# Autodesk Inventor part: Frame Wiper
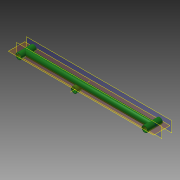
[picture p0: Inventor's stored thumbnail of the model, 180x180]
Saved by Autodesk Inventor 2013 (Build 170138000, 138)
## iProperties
Created: 2006-03
Part Number: Frame Wiper
Document SubType Name: Modeling
Designer: Autodesk, Inc.
Material: Stainless Steel, 440C
Mass: 450.336 g
Surface Area: 586.145 cm^2
Volume: 58.1078 cm^3
Density: 7.75 g/cm^3
Author: Autodesk, Inc.
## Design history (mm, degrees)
sketch "Sketch1"
  geometry: L1 (0, -28.185)-(0, 16.364) reference; L2 (-305.6, 0)-(307.6, 0) reference; C1 r 10 at (210, 0); 1 further point
  constraints: 1 centre point
  dimensions: "d3" = 20 diameter of C1; "d6" = 210 distance of C1.centre point (0, 0)
extrude "Extrusion1" new body sketch "Sketch1" stored distance "d4" = 50; taper "d5" = 0 deg
sketch "Sketch3"
  geometry: C1 r 10 at (0, 0); 1 further point
  constraints: 1 centre point, 1 coincident
  dimensions: "d8" = 20 diameter of C1
extrude "Extrusion2" join sketch "Sketch3" stored distance "d9" = 50; taper "d10" = 0 deg
mirror "Mirror1"
shell "Shell1" dims "d11" = 2
sketch "Sketch4"
  geometry: C1 r 10 at (32.287, -11.821); A1 r 8 centre (-210, 0) between (-210, -8) and (-210, 8) reference; 1 further point
  constraints: 1 centre point
  dimensions: "d13" = 242.575 distance of C1.centre A1.centre; "d14" = 20 diameter of C1; "d21" = 11.821 vertical distance of point (0, 0) C1.centre
workaxis "Work Axis1"
node "Ref"
sketch "Sketch5"
  geometry: C1 r 8 at (210, 0) reference; C2 r 8 at (-210, 0) reference; 1 further point
node "Bearing"
node "Ref_Wiper"
workaxis "Work Axis2"
sketch "Sketch6"
  geometry: C1 r 10 at (32.287, -11.821); C2 r 8 at (32.287, -11.821); 1 further point
  constraints: 2 centre point
  dimensions: "d24" = 20 diameter of C1; "d25" = 32.2868 horizontal distance of point (0, 0) C1.centre (derived); "d26" = 11.821 vertical distance of C1.centre point (0, 0) (derived); "d27" = 16 diameter of C2 (computed from d24)
extrude "Extrusion3" join sketch "Sketch6" distance "d22" = 18; taper "d23" = 0 deg
body "Solid1"
other parameters: "d16" = 0, "d20" = 8
